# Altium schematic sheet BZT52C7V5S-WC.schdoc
size 127 x 101 mm
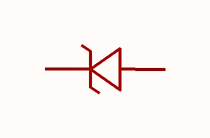
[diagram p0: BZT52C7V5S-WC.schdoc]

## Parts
D?  bzt52c7v5s_c523831  [SOD-323_L1.6-W1.3-LS2.7-RD]  (value not drawn)

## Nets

Not connected (* = marked no-connect by the designer): D? 1(K) 2(A)

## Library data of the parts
D? = bzt52c7v5s_c523831: 二极管配置:1个独立式;稳压值(标称值):7.5V;稳压值(范围):7V~7.9V;耗散功率(Pd):200mW;; Manufacturer: MDD(辰达半导体); Symbol: BZT52C7V5S-WC; AddInBom: yes; ModelId: 39bca86493a8419684ee2090e9340edf; ModelTransform: 104.3305,51.181,0,0,0,0,0,0,0; Diode Configuration: 1个独立式; Zener Voltage(Nom): 7.5V; Reverse Leakage Current (Ir): 500nA; Pd - Power Dissipation: 200mW; Impedance(Zzt): 30Ω; Tolerance: ±5%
